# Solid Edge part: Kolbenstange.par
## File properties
Username: bmolnar
Dokumentum tartalom típus: 0
Author: bmolnar
Last saved by: bmolnar
Revision: 81
Sűrűség: 0,000 kg/m^3
Pontosság: 0,990
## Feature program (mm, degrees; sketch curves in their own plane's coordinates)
base feature "unnamed BaseFeature 1"
sketch for "unnamed Protrusion 1" plane through (23.3, 0, 0) normal (1, 0, 0) x-axis (0, -1, 0)
  circle centre (0, 0) radius 10
extrude "unnamed Protrusion 1" add finite 13.4 along +normal
sketch for "Furat_2" plane through (-10, 0, 0) normal (-1, 0, 0) x-axis (0, 1, 0)
hole "Furat_2" diameter 6 finite  VBottomAngle = 118 deg; ThreadDepth = 15 mm; StartChamferOffset = 0.7 mm; StartChamferAngle = 45 deg
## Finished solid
Body 1: solid body, 14 faces, 20 edges, 8 vertices.
  Faces by surface: plane 7, cylinder 4, cone 2, torus 1
  Edges by curve: circle 10, line 6, ellipse 2, intersection 2
Bounding box of the edges (mm; curved faces can reach further): 46.700 x 20.000 x 20.000, from (-10, -10, -10) to (36.7, 10, 10).
Cylindrical faces by radius (mm): R2.4585 x2, R5 x1, R10 x1
Conical faces (half-angle, radius in mm at the cone's reference point): 45 deg R3.1585 x1, 59 deg R2.4585 x1
Toroidal faces (ring radius, tube radius in mm): R3.8 r1.2 x1
Planar faces by outward normal: +x 1, +z 1, -x 2, -z 1, oblique 2
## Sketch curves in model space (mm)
circle centre (23.3, 0, 0) radius 10
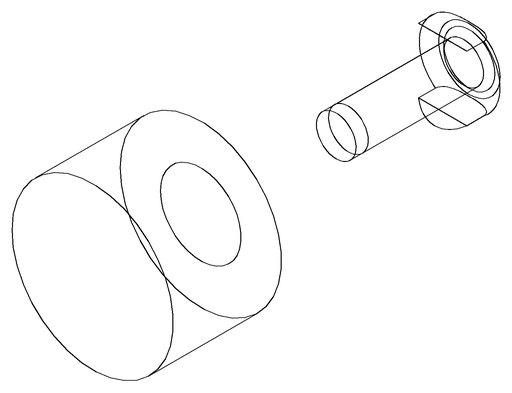
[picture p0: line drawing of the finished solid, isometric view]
